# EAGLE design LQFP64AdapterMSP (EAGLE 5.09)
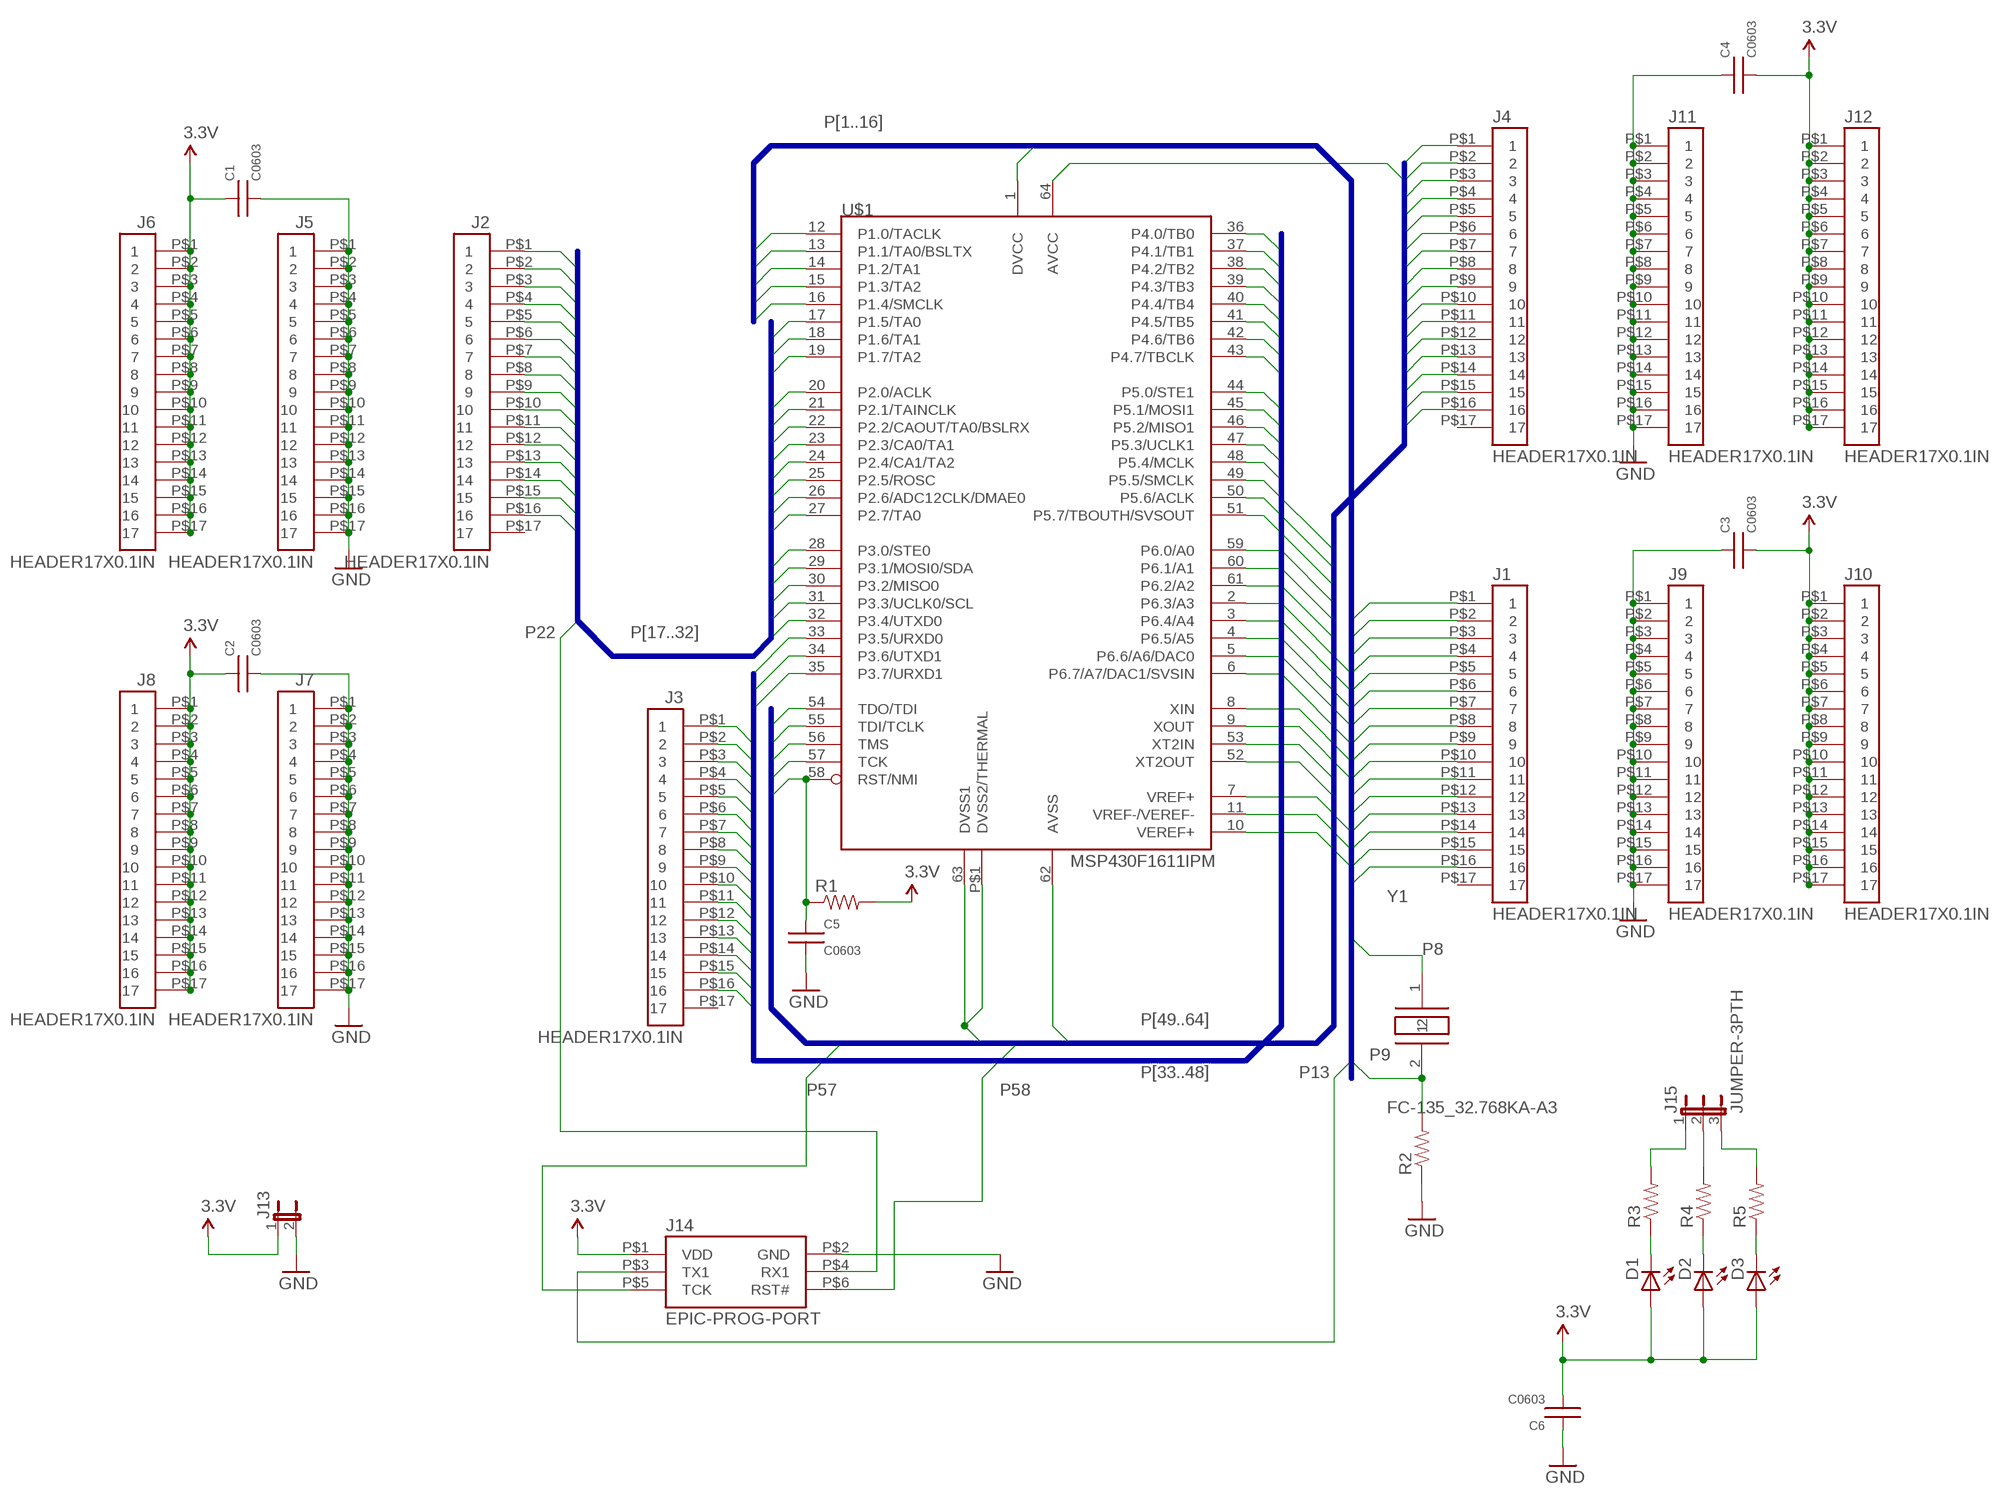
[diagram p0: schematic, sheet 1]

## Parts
C1  C0603  [C0603]
C2  C0603  [C0603]
C3  C0603  [C0603]
C4  C0603  [C0603]
C5  C0603  [C0603]
C6  C0603  [C0603]
D1  LED0603  [LED-0603]
D2  LED0603  [LED-0603]
D3  LED0603  [LED-0603]
J1  HEADER17X0.1IN  [HEADER17X0.1IN]
J2  HEADER17X0.1IN  [HEADER17X0.1IN]
J3  HEADER17X0.1IN  [HEADER17X0.1IN]
J4  HEADER17X0.1IN  [HEADER17X0.1IN]
J5  HEADER17X0.1IN  [HEADER17X0.1IN]
J6  HEADER17X0.1IN  [HEADER17X0.1IN]
J7  HEADER17X0.1IN  [HEADER17X0.1IN]
J8  HEADER17X0.1IN  [HEADER17X0.1IN]
J9  HEADER17X0.1IN  [HEADER17X0.1IN]
J10  HEADER17X0.1IN  [HEADER17X0.1IN]
J11  HEADER17X0.1IN  [HEADER17X0.1IN]
J12  HEADER17X0.1IN  [HEADER17X0.1IN]
J13  JUMPER-2PTH  [1X02]
J14  EPIC-PROG-PORT  [HEADER2X3X2MM]
J15  JUMPER-3PTH  [1X03]
R1  RESISTOR0603-RES  [0603-RES]
R2  RESISTOR0603-RES  [0603-RES]
R3  RESISTOR0603-RES  [0603-RES]
R4  RESISTOR0603-RES  [0603-RES]
R5  RESISTOR0603-RES  [0603-RES]
U$1  MSP430F1611IPM  [PM/PAG64]
Y1  FC-135_32.768KA-A3  [FC-135]

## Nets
3.3V: C1.1 C2.1 C3.2 C4.2 C6.2 D1.A D2.A D3.A J6.P$1 J6.P$2 J6.P$3 J6.P$4 J6.P$5 J6.P$6 J6.P$7 J6.P$8 J6.P$9 J6.P$10 J6.P$11 J6.P$12 J6.P$13 J6.P$14 J6.P$15 J6.P$16 J6.P$17 J8.P$1 J8.P$2 J8.P$3 J8.P$4 J8.P$5 J8.P$6 J8.P$7 J8.P$8 J8.P$9 J8.P$10 J8.P$11 J8.P$12 J8.P$13 J8.P$14 J8.P$15 J8.P$16 J8.P$17 J10.P$1 J10.P$2 J10.P$3 J10.P$4 J10.P$5 J10.P$6 J10.P$7 J10.P$8 J10.P$9 J10.P$10 J10.P$11 J10.P$12 J10.P$13 J10.P$14 J10.P$15 J10.P$16 J10.P$17 J12.P$1 J12.P$2 J12.P$3 J12.P$4 J12.P$5 J12.P$6 J12.P$7 J12.P$8 J12.P$9 J12.P$10 J12.P$11 J12.P$12 J12.P$13 J12.P$14 J12.P$15 J12.P$16 J12.P$17 J13.1 J14.P$1(VDD) R1.2
GND: C1.2 C2.2 C3.1 C4.1 C5.2 C6.1 J5.P$1 J5.P$2 J5.P$3 J5.P$4 J5.P$5 J5.P$6 J5.P$7 J5.P$8 J5.P$9 J5.P$10 J5.P$11 J5.P$12 J5.P$13 J5.P$14 J5.P$15 J5.P$16 J5.P$17 J7.P$1 J7.P$2 J7.P$3 J7.P$4 J7.P$5 J7.P$6 J7.P$7 J7.P$8 J7.P$9 J7.P$10 J7.P$11 J7.P$12 J7.P$13 J7.P$14 J7.P$15 J7.P$16 J7.P$17 J9.P$1 J9.P$2 J9.P$3 J9.P$4 J9.P$5 J9.P$6 J9.P$7 J9.P$8 J9.P$9 J9.P$10 J9.P$11 J9.P$12 J9.P$13 J9.P$14 J9.P$15 J9.P$16 J9.P$17 J11.P$1 J11.P$2 J11.P$3 J11.P$4 J11.P$5 J11.P$6 J11.P$7 J11.P$8 J11.P$9 J11.P$10 J11.P$11 J11.P$12 J11.P$13 J11.P$14 J11.P$15 J11.P$16 J11.P$17 J13.2 J14.P$2(GND) R2.1
N$1: D1.C R3.1
N$2: D2.C R4.1
N$3: D3.C R5.1
N$4: J15.1 R3.2
N$5: J15.2 R4.2
N$6: J15.3 R5.2
P1: J1.P$1 U$1.1(DVCC)
P2: J1.P$2 U$1.2(P6.3/A3)
P3: J1.P$3 U$1.3(P6.4/A4)
P4: J1.P$4 U$1.4(P6.5/A5)
P5: J1.P$5 U$1.5(P6.6/A6/DAC0)
P6: J1.P$6 U$1.6(P6.7/A7/DAC1/SVSIN)
P7: J1.P$7 U$1.7(VREF+)
P8: J1.P$8 U$1.8(XIN) Y1.1
P9: J1.P$9 R2.2 U$1.9(XOUT) Y1.2
P10: J1.P$10 U$1.10(VEREF+)
P11: J1.P$11 U$1.11(VREF-/VEREF-)
P12: J1.P$12 U$1.12(P1.0/TACLK)
P13: J1.P$13 J14.P$3(TX1) U$1.13(P1.1/TA0/BSLTX)
P14: J1.P$14 U$1.14(P1.2/TA1)
P15: J1.P$15 U$1.15(P1.3/TA2)
P16: J1.P$16 U$1.16(P1.4/SMCLK)
P17: J2.P$1 U$1.17(P1.5/TA0)
P18: J2.P$2 U$1.18(P1.6/TA1)
P19: J2.P$3 U$1.19(P1.7/TA2)
P20: J2.P$4 U$1.20(P2.0/ACLK)
P21: J2.P$5 U$1.21(P2.1/TAINCLK)
P22: J2.P$6 J14.P$4(RX1) U$1.22(P2.2/CAOUT/TA0/BSLRX)
P23: J2.P$7 U$1.23(P2.3/CA0/TA1)
P24: J2.P$8 U$1.24(P2.4/CA1/TA2)
P25: J2.P$9 U$1.25(P2.5/ROSC)
P26: J2.P$10 U$1.26(P2.6/ADC12CLK/DMAE0)
P27: J2.P$11 U$1.27(P2.7/TA0)
P28: J2.P$12 U$1.28(P3.0/STE0)
P29: J2.P$13 U$1.29(P3.1/MOSI0/SDA)
P30: J2.P$14 U$1.30(P3.2/MISO0)
P31: J2.P$15 U$1.31(P3.3/UCLK0/SCL)
P32: J2.P$16 U$1.32(P3.4/UTXD0)
P33: J3.P$1 U$1.33(P3.5/URXD0)
P34: J3.P$2 U$1.34(P3.6/UTXD1)
P35: J3.P$3 U$1.35(P3.7/URXD1)
P36: J3.P$4 U$1.36(P4.0/TB0)
P37: J3.P$5 U$1.37(P4.1/TB1)
P38: J3.P$6 U$1.38(P4.2/TB2)
P39: J3.P$7 U$1.39(P4.3/TB3)
P40: J3.P$8 U$1.40(P4.4/TB4)
P41: J3.P$9 U$1.41(P4.5/TB5)
P42: J3.P$10 U$1.42(P4.6/TB6)
P43: J3.P$11 U$1.43(P4.7/TBCLK)
P44: J3.P$12 U$1.44(P5.0/STE1)
P45: J3.P$13 U$1.45(P5.1/MOSI1)
P46: J3.P$14 U$1.46(P5.2/MISO1)
P47: J3.P$15 U$1.47(P5.3/UCLK1)
P48: J3.P$16 U$1.48(P5.4/MCLK)
P49: J4.P$1 U$1.49(P5.5/SMCLK)
P50: J4.P$2 U$1.50(P5.6/ACLK)
P51: J4.P$3 U$1.51(P5.7/TBOUTH/SVSOUT)
P52: J4.P$4 U$1.52(XT2OUT)
P53: J4.P$5 U$1.53(XT2IN)
P54: J4.P$6 U$1.54(TDO/TDI)
P55: J4.P$7 U$1.55(TDI/TCLK)
P56: J4.P$8 U$1.56(TMS)
P57: J4.P$9 J14.P$5(TCK) U$1.57(TCK)
P58: C5.1 J4.P$10 J14.P$6(RST#) R1.1 U$1.58(RST/NMI)
P59: J4.P$11 U$1.59(P6.0/A0)
P60: J4.P$12 U$1.60(P6.1/A1)
P61: J4.P$13 U$1.61(P6.2/A2)
P62: J4.P$14 U$1.62(AVSS)
P63: J4.P$15 U$1.63(DVSS1) U$1.P$1(DVSS2/THERMAL)
P64: J4.P$16 U$1.64(AVCC)
Unconnected: J1.P$17 J2.P$17 J3.P$17 J4.P$17

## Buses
P[17..32]
P[33..48]
P[49..64]
P[1..16]

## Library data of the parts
C1-C6 = umich:C
D1-D3 = umich:LED: LEDs
J1-J12 = berkeley-epic:HEADER17X0.1IN
J13 = umich:JUMPER-2: Jumper
J14 = berkeley-epic:EPIC-PROG-PORT
J15 = umich:JUMPER-3
R1-R5 = SparkFun:RESISTOR: Resistor
U$1 = Thomas:MSP430F1611
Y1 = berkeley-epic:FC-135_32.768KA-A3

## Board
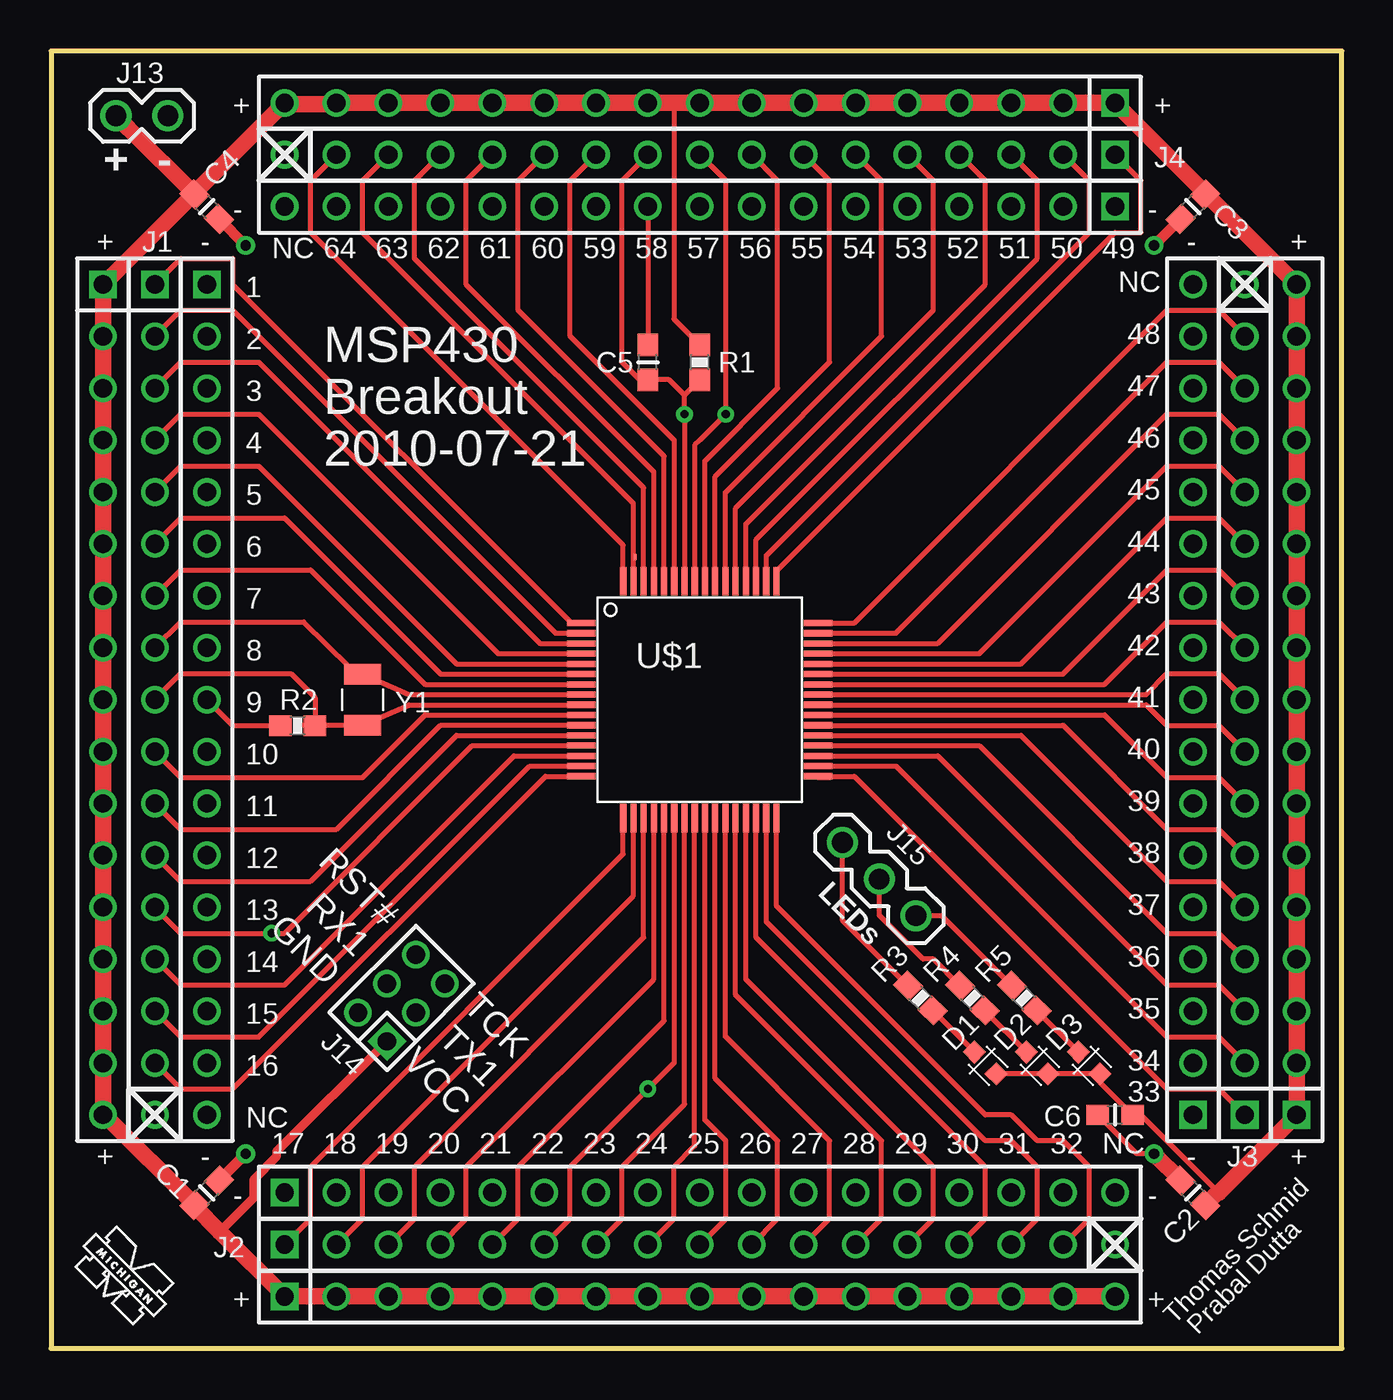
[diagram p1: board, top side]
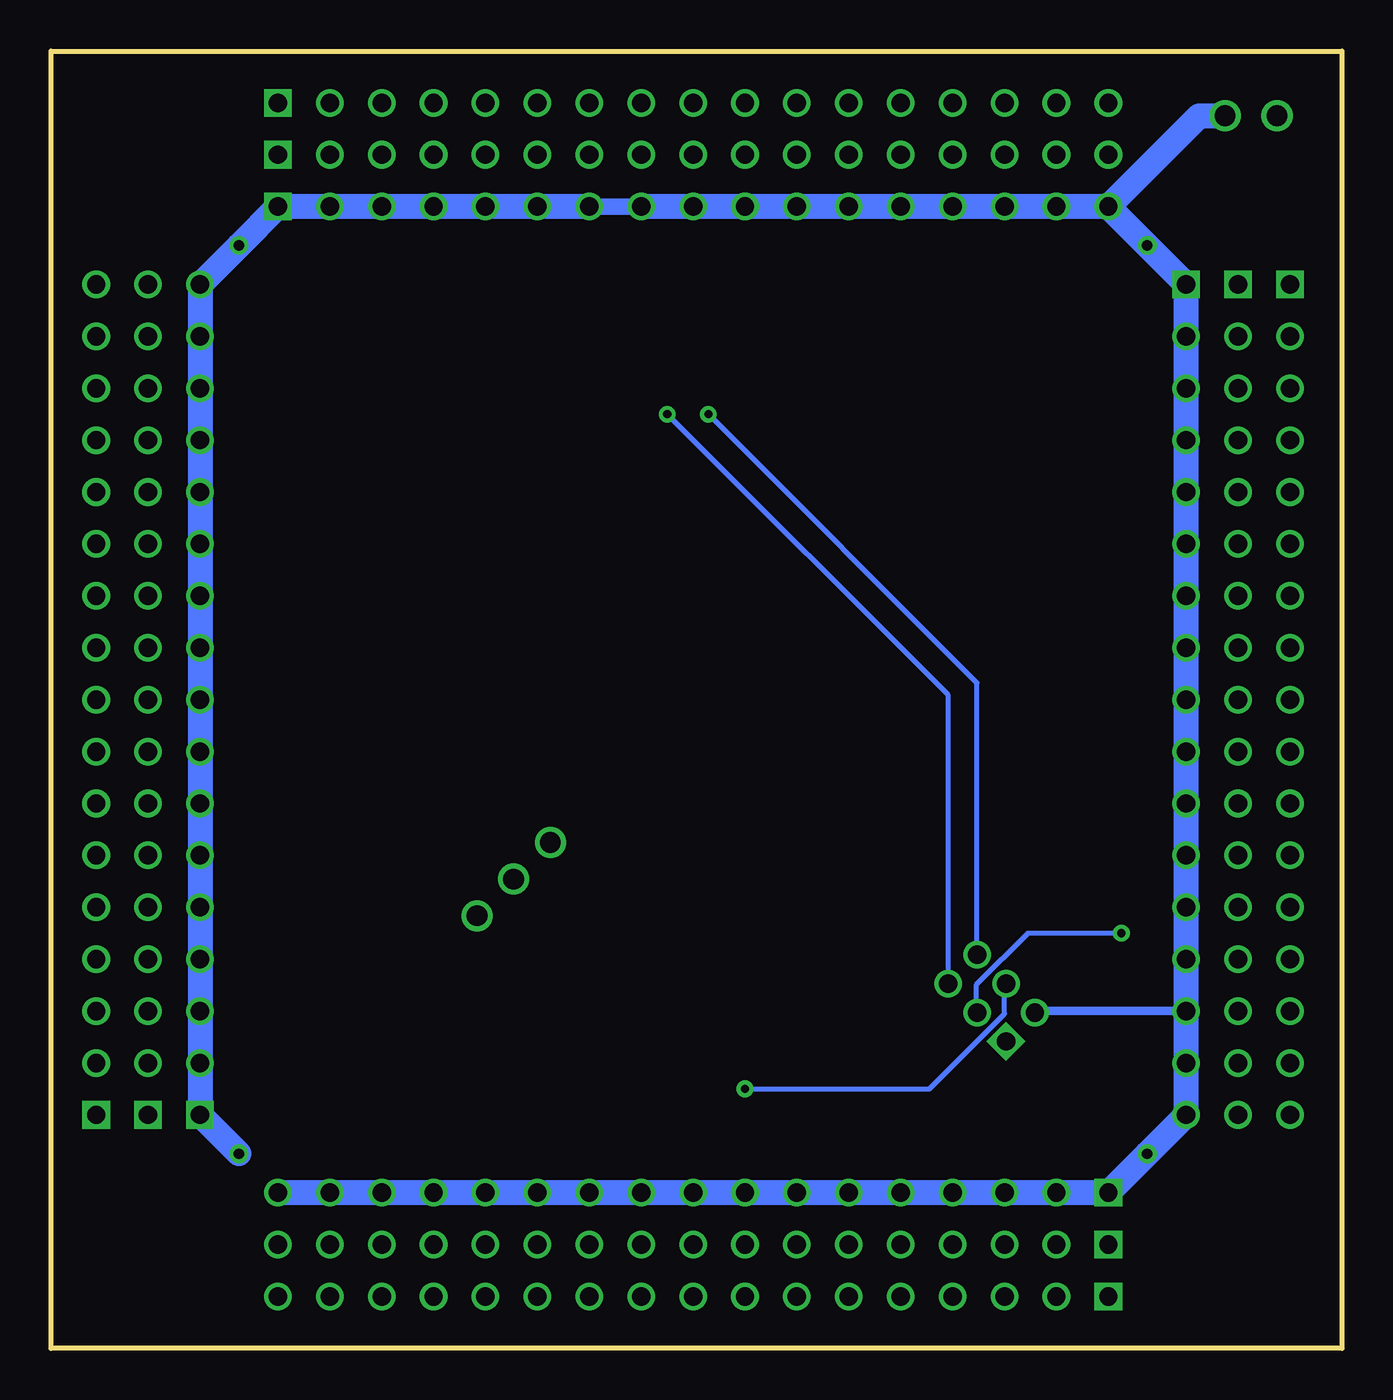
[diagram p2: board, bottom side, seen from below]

Size 63.17 x 63.49 mm. Coordinates in mm from the lower left corner, seen from the top.
Outline: 0,0 63.17,0 63.17,63.49 0,63.49 0,0
Copper layers (1*16): Top 0.0178mm / dielectric 1.4986mm / Bottom 0.0178mm
Design rules "SSC-EAGLE-2Lyr_v1.0.0.3": minimum track width 6mil, minimum drill 14mil, track to track 6mil, track to pad 6mil, pad to pad 6mil, via to via 6mil, smd to smd 6mil, copper to edge 20mil, drill to drill 16mil, minimum pad ring 8mil, minimum via ring 8mil, stop-mask expansion 3mil, vias tented up to drill 0mil, thermal gap 10mil

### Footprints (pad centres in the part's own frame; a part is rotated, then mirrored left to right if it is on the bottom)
C0603 = smd 1.1 x 1: 1 -0.85,0; 2 0.85,0
LED-0603 = smd 0.8 x 0.8: A 0,-0.75; C 0,0.75
HEADER17X0.1IN = drill 0.9 square: P$1 -20.32,0 | drill 0.9 round: P$2 -17.78,0; P$3 -15.24,0; P$4 -12.7,0; P$5 -10.16,0; P$6 -7.62,0; P$7 -5.08,0; P$8 -2.54,0; P$9 0,0; P$10 2.54,0; P$11 5.08,0; P$12 7.62,0; P$13 10.16,0; P$14 12.7,0; P$15 15.24,0; P$16 17.78,0; P$17 20.32,0
1X02 = drill 1.016 round: 1 0,0; 2 2.54,0
HEADER2X3X2MM = drill 0.9 square: P$1 -1,2 | drill 0.9 round: P$2 1,2; P$3 -1,0; P$4 1,0; P$5 -1,-2; P$6 1,-2
1X03 = drill 1.016 round: 1 0,0; 2 2.54,0; 3 5.08,0
0603-RES = smd 1.1 x 1: 1 -0.85,0; 2 0.85,0
PM/PAG64 = smd 1.4 x 0.3: 1 -5.8,3.75; 2 -5.8,3.25; 3 -5.8,2.75; 4 -5.8,2.25; 5 -5.8,1.75; 6 -5.8,1.25; 7 -5.8,0.75; 8 -5.8,0.25; 9 -5.8,-0.25; 10 -5.8,-0.75; 11 -5.8,-1.25; 12 -5.8,-1.75; 13 -5.8,-2.25; 14 -5.8,-2.75; 15 -5.8,-3.25; 16 -5.8,-3.75; 33 5.8,-3.75; 34 5.8,-3.25; 35 5.8,-2.75; 36 5.8,-2.25; 37 5.8,-1.75; 38 5.8,-1.25; 39 5.8,-0.75; 40 5.8,-0.25; 41 5.8,0.25; 42 5.8,0.75; 43 5.8,1.25; 44 5.8,1.75; 45 5.8,2.25; 46 5.8,2.75; 47 5.8,3.25; 48 5.8,3.75 | smd 0.3 x 1.4: 17 -3.75,-5.8; 18 -3.25,-5.8; 19 -2.75,-5.8; 20 -2.25,-5.8; 21 -1.75,-5.8; 22 -1.25,-5.8; 23 -0.75,-5.8; 24 -0.25,-5.8; 25 0.25,-5.8; 26 0.75,-5.8; 27 1.25,-5.8; 28 1.75,-5.8; 29 2.25,-5.8; 30 2.75,-5.8; 31 3.25,-5.8; 32 3.75,-5.8; 49 3.75,5.8; 50 3.25,5.8; 51 2.75,5.8; 52 2.25,5.8; 53 1.75,5.8; 54 1.25,5.8; 55 0.75,5.8; 56 0.25,5.8; 57 -0.25,5.8; 58 -0.75,5.8; 59 -1.25,5.8; 60 -1.75,5.8; 61 -2.25,5.8; 62 -2.75,5.8; 63 -3.25,5.8; 64 -3.75,5.8 | smd 0.152 x 0.305: P$1 -3.175,6.985
FC-135 = smd 1 x 1.8: 1 -1.25,0; 2 1.25,0

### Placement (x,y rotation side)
C1  7.62,7.62 45 top
C2  55.88,7.62 135 top
C3  55.88,55.88 45 top
C4  7.62,55.88 135 top
C5  29.21,48.26 90 top
C6  52.07,11.43 0 top
D1  45.72,13.97 45 top
D2  48.26,13.97 45 top
D3  50.8,13.97 45 top
J1  5.08,31.75 270 top
J2  31.75,5.08 0 top
J3  58.42,31.75 90 top
J4  31.75,58.42 180 top
J5  31.75,7.62 0 top
J6  31.75,2.54 0 top
J7  55.88,31.75 90 top
J8  60.96,31.75 90 top
J9  7.62,31.75 270 top
J10  2.54,31.75 270 top
J11  31.75,55.88 180 top
J12  31.75,60.96 180 top
J13  3.17,60.33 0 top
J14  17.14,17.14 135 top
J15  38.73,24.77 315 top
R1  31.75,48.26 90 top
R2  12.06,30.48 0 top
R3  42.55,17.14 135 top
R4  45.09,17.14 135 top
R5  47.62,17.14 135 top
U$1  31.75,31.75 0 top
U$2  [UMICH]  0.64,4.19 315 top
Y1  15.24,31.75 270 top

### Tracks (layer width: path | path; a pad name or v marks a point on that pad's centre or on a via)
3.3V
  Top 0.254: R1.2 30.48,50.38 30.48,60.96 | 57.08,7.62 57.15,7.62 53.34,11.43 C6.2 51.33,13.02 D3.A D2.A D1.A | J8.P$17 60.89,52.07 C3.2 | J12.P$16 13.9,60.89 | J12.P$10 J12.P$9
  Top 0.406: 8.26,5.71 9.91,7.37 9.91,8.26 11.05,9.4 11.05,9.63 J14.P$1
  Top 0.508: 2.61,11.43 J10.P$17 | C1.1 7.02,6.95 | J10.P$13 J10.P$12 2.54,25.4 | C4.2 11.43,60.89 J12.P$17 J12.P$16 | J12.P$10 30.48,60.96 J12.P$9 J12.P$8 | J12.P$5 J12.P$4 J12.P$3
  Top 0.813: 7.02,6.95 8.26,5.71 J6.P$1 J6.P$2 J6.P$3 J6.P$4 J6.P$5 J6.P$6 J6.P$7 J6.P$8 J6.P$9 J6.P$10 J6.P$11 J6.P$12 J6.P$13 J6.P$14 J6.P$15 J6.P$16 J6.P$17 | J10.P$17 J10.P$16 J10.P$15 J10.P$14 J10.P$13 2.54,25.4 J10.P$11 J10.P$10 J10.P$9 J10.P$8 J10.P$7 J10.P$6 J10.P$5 J10.P$4 J10.P$3 J10.P$2 J10.P$1 J12.P$17 | J12.P$16 J12.P$15 J12.P$14 J12.P$13 J12.P$12 J12.P$11 J12.P$10 J12.P$8 J12.P$7 J12.P$6 J12.P$5 J12.P$3 J12.P$2 J12.P$1 J8.P$17 J8.P$16 J8.P$15 J8.P$14 J8.P$13 J8.P$12 J8.P$11 J8.P$10 J8.P$9 J8.P$8 J8.P$7 J8.P$6 J8.P$5 J8.P$4 J8.P$3 J8.P$2 J8.P$1 57.15,7.62 | J13.1 3.81,59.69 C4.2 | C1.1 2.61,11.43 | 57.08,7.62 C2.1 | 11.43,60.89 13.9,60.89
GND  (via drill 0.51)
  Top 0.254: R2.1 8.89,30.48 J9.P$9 | J11.P$10 C5.2 | v53.98,9.53 53.12,9.53 C6.1
  Top 0.508: C1.2 v9.53,9.53 | v9.53,53.98 C4.1 | v53.98,53.98 C3.1
  Top 0.813: v53.98,9.53 C2.2
  Bottom 0.406: J9.P$15 14.95,16.51 J14.P$2
  Bottom 0.508: J5.P$13 J5.P$14 J5.P$15
  Bottom 0.813: J11.P$8 J11.P$7
  Bottom 1.219: J5.P$17 J5.P$16 J5.P$15 J5.P$13 J5.P$12 J5.P$11 J5.P$10 J5.P$9 J5.P$8 J5.P$7 J5.P$6 J5.P$5 J5.P$4 J5.P$3 J5.P$2 J5.P$1 v9.53,9.53 J9.P$17 J9.P$16 J9.P$15 J9.P$14 J9.P$13 J9.P$12 J9.P$11 J9.P$10 J9.P$9 J9.P$8 J9.P$7 J9.P$6 J9.P$5 J9.P$4 J9.P$3 J9.P$2 J9.P$1 v9.53,53.98 J11.P$17 | v53.98,9.53 J7.P$1 J7.P$2 J7.P$3 J7.P$4 J7.P$5 J7.P$6 J7.P$7 J7.P$8 J7.P$9 J7.P$10 J7.P$11 J7.P$12 J7.P$13 J7.P$14 J7.P$15 J7.P$16 J7.P$17 v53.98,53.98 J11.P$1 J11.P$2 J11.P$3 J11.P$4 J11.P$5 J11.P$6 J11.P$7 | J11.P$17 J11.P$16 J11.P$15 J11.P$14 J11.P$13 J11.P$12 J11.P$11 J11.P$10 J11.P$9 J11.P$8 | J11.P$17 6.99,60.33 J13.2
N$1
  Top 0.254: R3.1 D1.C
N$2
  Top 0.254: R4.1 D2.C
N$3
  Top 0.254: R5.1 D3.C
N$4
  Top 0.254: J15.1 38.73,20.95 R3.2
N$5
  Top 0.254: J15.2 40.53,21.19 42.67,19.05 43.18,19.05 R4.2
N$6
  Top 0.254: J15.3 43.6,21.17 R5.2
P1
  Top 0.254: J1.P$1 6.35,53.34 8.89,53.34 8.89,52.07 25.46,35.5 U$1.1
P2
  Top 0.254: J1.P$2 6.35,50.8 8.89,50.8 24.68,35.01 25.4,35.01 U$1.2 | U$1.2 | U$1.2
P3
  Top 0.254: J1.P$3 6.35,48.26 10.16,48.26 23.92,34.5 U$1.3
P4
  Top 0.254: J1.P$4 6.35,45.72 10.16,45.72 21.88,34 U$1.4
P5
  Top 0.254: J1.P$5 6.35,43.18 10.16,43.18 19.84,33.5 U$1.5
P6
  Top 0.254: J1.P$6 6.35,40.64 11.43,40.64 19.07,33 U$1.6
P7
  Top 0.254: J1.P$7 6.35,38.1 12.7,38.1 18.3,32.5 U$1.7
P8
  Top 0.254: J1.P$8 6.35,35.56 12.36,35.56 14.61,33.34 14.94,33 Y1.1 17.51,32 U$1.8
P9
  Top 0.254: J1.P$9 6.35,33.02 11.75,33.02 12.91,31.85 R2.2 12.3,30.5 Y1.2 17.51,31.5 U$1.9
P10
  Top 0.254: J1.P$10 6.35,27.94 15.24,27.94 18.3,31 U$1.10
P11
  Top 0.254: J1.P$11 6.35,25.4 13.97,25.4 19.07,30.5 U$1.11
P12
  Top 0.254: J1.P$12 6.35,22.86 12.7,22.86 19.84,30 U$1.12
P13  (via drill 0.41)
  Top 0.254: J1.P$13 6.35,20.32 v10.79,20.32 11.43,20.32 20.61,29.5 U$1.13
  Bottom 0.254: J14.P$3 17.85,16.45 17.91,16.51 17.91,17.78 15.37,20.32 v10.79,20.32
P14
  Top 0.254: J1.P$14 6.35,17.78 11.43,17.78 22.65,29 U$1.14
P15
  Top 0.254: J1.P$15 6.35,15.24 10.16,15.24 23.42,28.5 U$1.15
P16
  Top 0.254: J1.P$16 6.35,12.7 8.89,12.7 24.19,28 U$1.16
P17
  Top 0.254: J2.P$1 12.7,6.35 12.7,8.89 28,24.19 U$1.17
P18
  Top 0.254: J2.P$2 15.24,6.35 15.24,8.89 28.5,22.15 U$1.18
P19
  Top 0.254: J2.P$3 17.78,6.35 17.78,8.89 29,20.11 U$1.19
P20
  Top 0.254: J2.P$4 20.32,6.35 20.32,8.89 29.5,18.07 U$1.20
P21
  Top 0.254: J2.P$5 22.86,6.35 22.86,8.89 30,16.03 U$1.21
P22  (via drill 0.41)
  Top 0.254: J2.P$6 25.4,6.35 25.4,8.89 v29.21,12.7 30.5,13.99 U$1.22
  Bottom 0.254: J14.P$4 16.51,17.78 16.51,16.38 20.19,12.7 v29.21,12.7 | J14.P$4
P23
  Top 0.254: J2.P$7 27.94,6.35 27.94,8.89 31,11.95 U$1.23
P24
  Top 0.254: J2.P$8 30.48,6.35 30.48,8.89 31.5,9.91 U$1.24
P25
  Top 0.254: J2.P$9 33.02,6.35 33.02,10.16 32,11.18 U$1.25
P26
  Top 0.254: J2.P$10 35.56,6.35 35.56,10.16 32.5,13.22 U$1.26
P27
  Top 0.254: J2.P$11 38.1,6.35 38.1,10.16 33,15.26 U$1.27
P28
  Top 0.254: J2.P$12 40.64,6.35 40.64,10.16 33.5,17.3 U$1.28
P29
  Top 0.254: J2.P$13 43.18,6.35 43.18,8.89 34,18.07 U$1.29
P30
  Top 0.254: J2.P$14 45.72,6.35 45.72,8.89 34.5,20.11 U$1.30
P31
  Top 0.254: J2.P$15 48.26,6.35 48.26,8.89 46.99,10.16 45.72,10.16 35,20.88 U$1.31
P32
  Top 0.254: J2.P$16 50.8,6.35 50.8,8.89 49.53,10.16 48.26,10.16 46.99,11.43 45.72,11.43 35.5,21.65 U$1.32
P33
  Top 0.254: J3.P$1 57.15,12.7 54.61,12.7 39.31,28 38.1,28 38.1,27.94 37.55,27.94 U$1.33
P34
  Top 0.254: J3.P$2 57.15,15.24 54.61,15.24 41.35,28.5 U$1.34
P35
  Top 0.254: J3.P$3 57.15,17.78 54.61,17.78 43.39,29 U$1.35
P36
  Top 0.254: J3.P$4 57.15,20.32 54.61,20.32 45.43,29.5 U$1.36
P37
  Top 0.254: J3.P$5 57.15,22.86 54.61,22.86 47.47,30 U$1.37
P38
  Top 0.254: 49.53,30.48 54.61,25.4 57.15,25.4 J3.P$6 | 49.53,30.48 49.51,30.5 | U$1.38 37.55,30.48 49.53,30.48
P39
  Top 0.254: J3.P$7 57.15,27.94 54.61,27.94 51.55,31 U$1.39
P40
  Top 0.254: J3.P$8 57.15,30.48 54.61,30.48 53.59,31.5 U$1.40
P41
  Top 0.254: J3.P$9 57.15,33.02 54.61,33.02 53.59,32 U$1.41
P42
  Top 0.254: J3.P$10 57.15,35.56 54.61,35.56 51.55,32.5 U$1.42
P43
  Top 0.254: J3.P$11 57.15,38.1 54.61,38.1 49.51,33 U$1.43
P44
  Top 0.254: J3.P$12 57.15,40.64 54.61,40.64 47.47,33.5 U$1.44
P45
  Top 0.254: J3.P$13 57.15,43.18 54.61,43.18 45.43,34 U$1.45
P46
  Top 0.254: J3.P$14 57.15,45.72 54.61,45.72 43.39,34.5 U$1.46
P47
  Top 0.254: J3.P$15 57.15,48.26 54.61,48.26 41.35,35 U$1.47
P48
  Top 0.254: J3.P$16 57.15,50.8 54.61,50.8 39.31,35.5 U$1.48
P49
  Top 0.254: J4.P$1 53.34,57.15 53.34,54.61 52.07,54.61 35.5,38.04 U$1.49
P50
  Top 0.254: J4.P$2 50.8,57.15 50.8,54.61 35,38.81 U$1.50
P51
  Top 0.254: J4.P$3 48.26,57.15 48.26,53.34 34.5,39.58 U$1.51
P52
  Top 0.254: J4.P$4 45.72,57.15 45.72,52.07 34,40.35 U$1.52
P53
  Top 0.254: J4.P$5 43.18,57.15 43.18,50.8 33.5,41.12 U$1.53
P54
  Top 0.254: J4.P$6 40.64,57.15 40.64,49.53 33,41.89 U$1.54
P55
  Top 0.254: J4.P$7 38.1,57.15 38.1,48.26 32.5,42.66 U$1.55
P56
  Top 0.254: J4.P$8 35.56,57.15 35.56,46.99 32,43.43 U$1.56
P57  (via drill 0.41)
  Top 0.254: J4.P$9 33.02,57.15 v33.02,45.72 31.75,44.45 31.5,44.2 U$1.57
  Bottom 0.254: J14.P$5 19.27,31.97 v33.02,45.72
P58  (via drill 0.41)
  Top 0.254: 31,46.66 30.25,47.41 C5.1 28.79,47.41 27.94,48.26 27.94,57.15 J4.P$10 | 31,46.66 v31,45.72 U$1.58 | 31,46.66 R1.1
  Bottom 0.254: J14.P$6 17.85,32.57 v31,45.72
P59
  Top 0.254: J4.P$11 25.4,57.15 25.4,49.53 30.48,44.45 30.5,44.43 U$1.59
P60
  Top 0.254: J4.P$12 22.86,57.15 22.86,50.8 30,43.66 U$1.60
P61
  Top 0.254: J4.P$13 20.32,57.15 20.32,52.07 29.21,43.18 29.5,42.89 U$1.61
P62
  Top 0.254: J4.P$14 17.78,57.15 17.78,53.34 29,42.12 U$1.62
P63
  Top 0: 28.5,38.66 U$1.P$1
  Top 0.254: J4.P$15 15.24,57.15 15.24,54.61 28.5,41.35 U$1.63 28.5,38.66
P64
  Top 0.254: J4.P$16 12.7,57.15 12.7,54.61 27.94,39.37 28,39.31 U$1.64

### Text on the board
tPlace: + | + | + | - | - | - | + | - | - | + | NC | 64 | 63 | 62 | 61 | 60 | 59 | 58 | 57 | 56 | 55 | 54 | 53 | 52 | 51 | 50 | 49 | NC | 1 | 48 | 2 | MSP430 | 47 | 3 | Breakout | 46 | 4 | 2010-07-21 | 45 | 5 | 44 | 6 | 43 | 7 | 42 | 8 | 41 | 9 | 40 | 10 | 39 | 11 | 38 | 12 | LEDs | 37 | 13 | 36 | 14 | 35 | 15 | 34 | 16 | 33 | NC | 17 | 18 | 19 | 20 | 21 | 22 | 23 | 24 | 25 | 26 | 27 | 28 | 29 | 30 | 31 | 32 | NC | + | - | - | + | - | - | + | + | Thomas Schmid | Prabal Dutta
